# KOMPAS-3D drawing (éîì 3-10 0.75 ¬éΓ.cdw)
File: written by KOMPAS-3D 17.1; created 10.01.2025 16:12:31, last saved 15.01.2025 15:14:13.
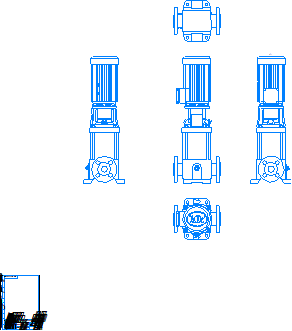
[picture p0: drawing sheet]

Sheet 1: A4, portrait

Title block, sheet 1: name: ВМН 3-10 0.75 кВт; designation: ВМН 3-10 0.75 кВт; material: Сталь 10  ГОСТ 1050-2013; mass: 68,16; sheets: 1; sheet format: A4; stored path: \\adlc.lan\data\АДЛ_ПКД\3D-модели\ADL production\Насосы ГРАНПАМП\Насосы ВМН\ВМН3\KOMPAS 3D\3-10 0.75 кВт _ ВМН.cdw

Views: Вид 1, Спереди, Проекционный вид 2, Проекционный вид 3, Проекционный вид 4, Проекционный вид 5
Referenced files in \\adlc.lan\data\АДЛ_ПКД\3D-модели\ADL production\Насосы ГРАНПАМП\Насосы ВМН\ВМН3\KOMPAS 3D\: ВМН 3-10 0,75 кВт.m3d
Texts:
  Andrey
  АДЛ
Dimensions and other numbers on the sheet: 1:1; 1; 68,16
